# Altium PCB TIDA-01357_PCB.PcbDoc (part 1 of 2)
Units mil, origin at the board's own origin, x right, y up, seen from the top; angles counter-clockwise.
Board outline 1710 x 2300 mil, 4 copper layers (Top Layer, Mid Layer 1, Mid Layer 2, Bottom Layer), stack 79.8 mil thick; 69 components, 66 nets, 243 pads, 213 vias.
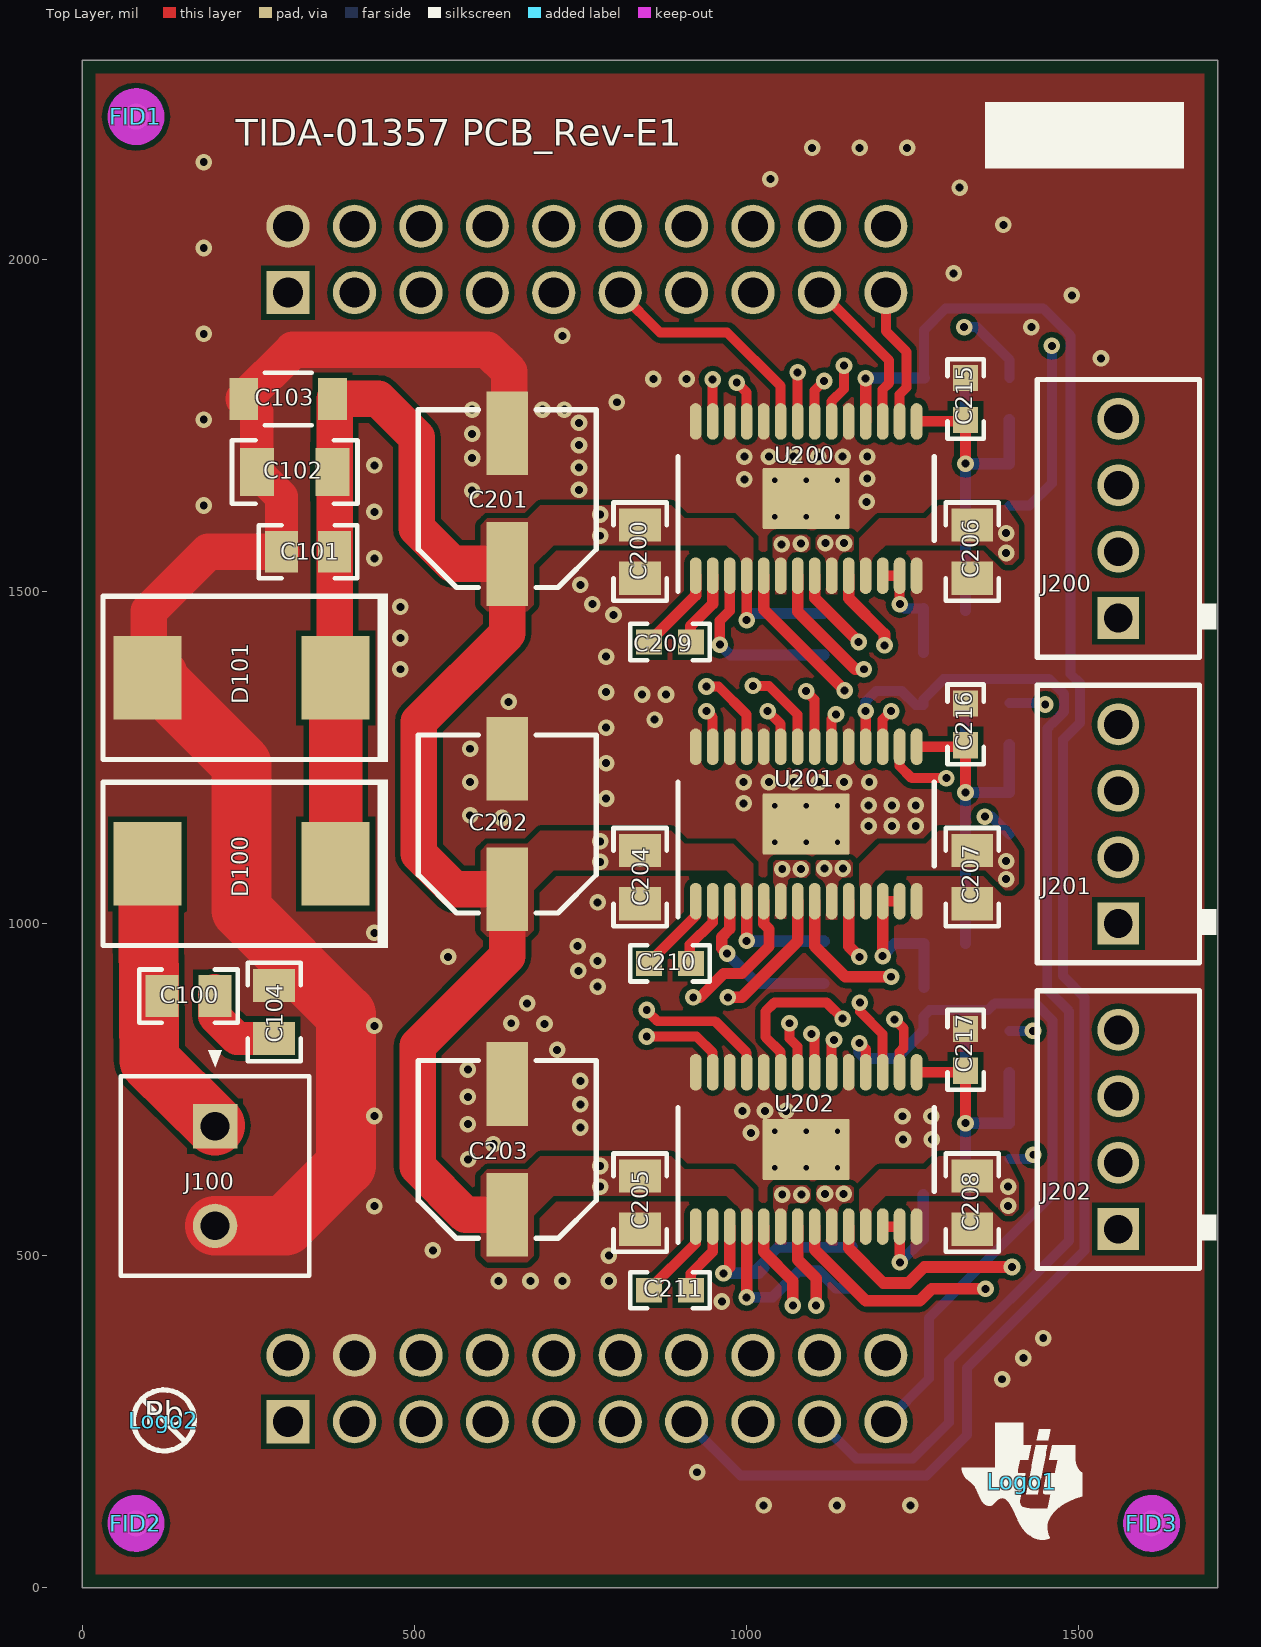
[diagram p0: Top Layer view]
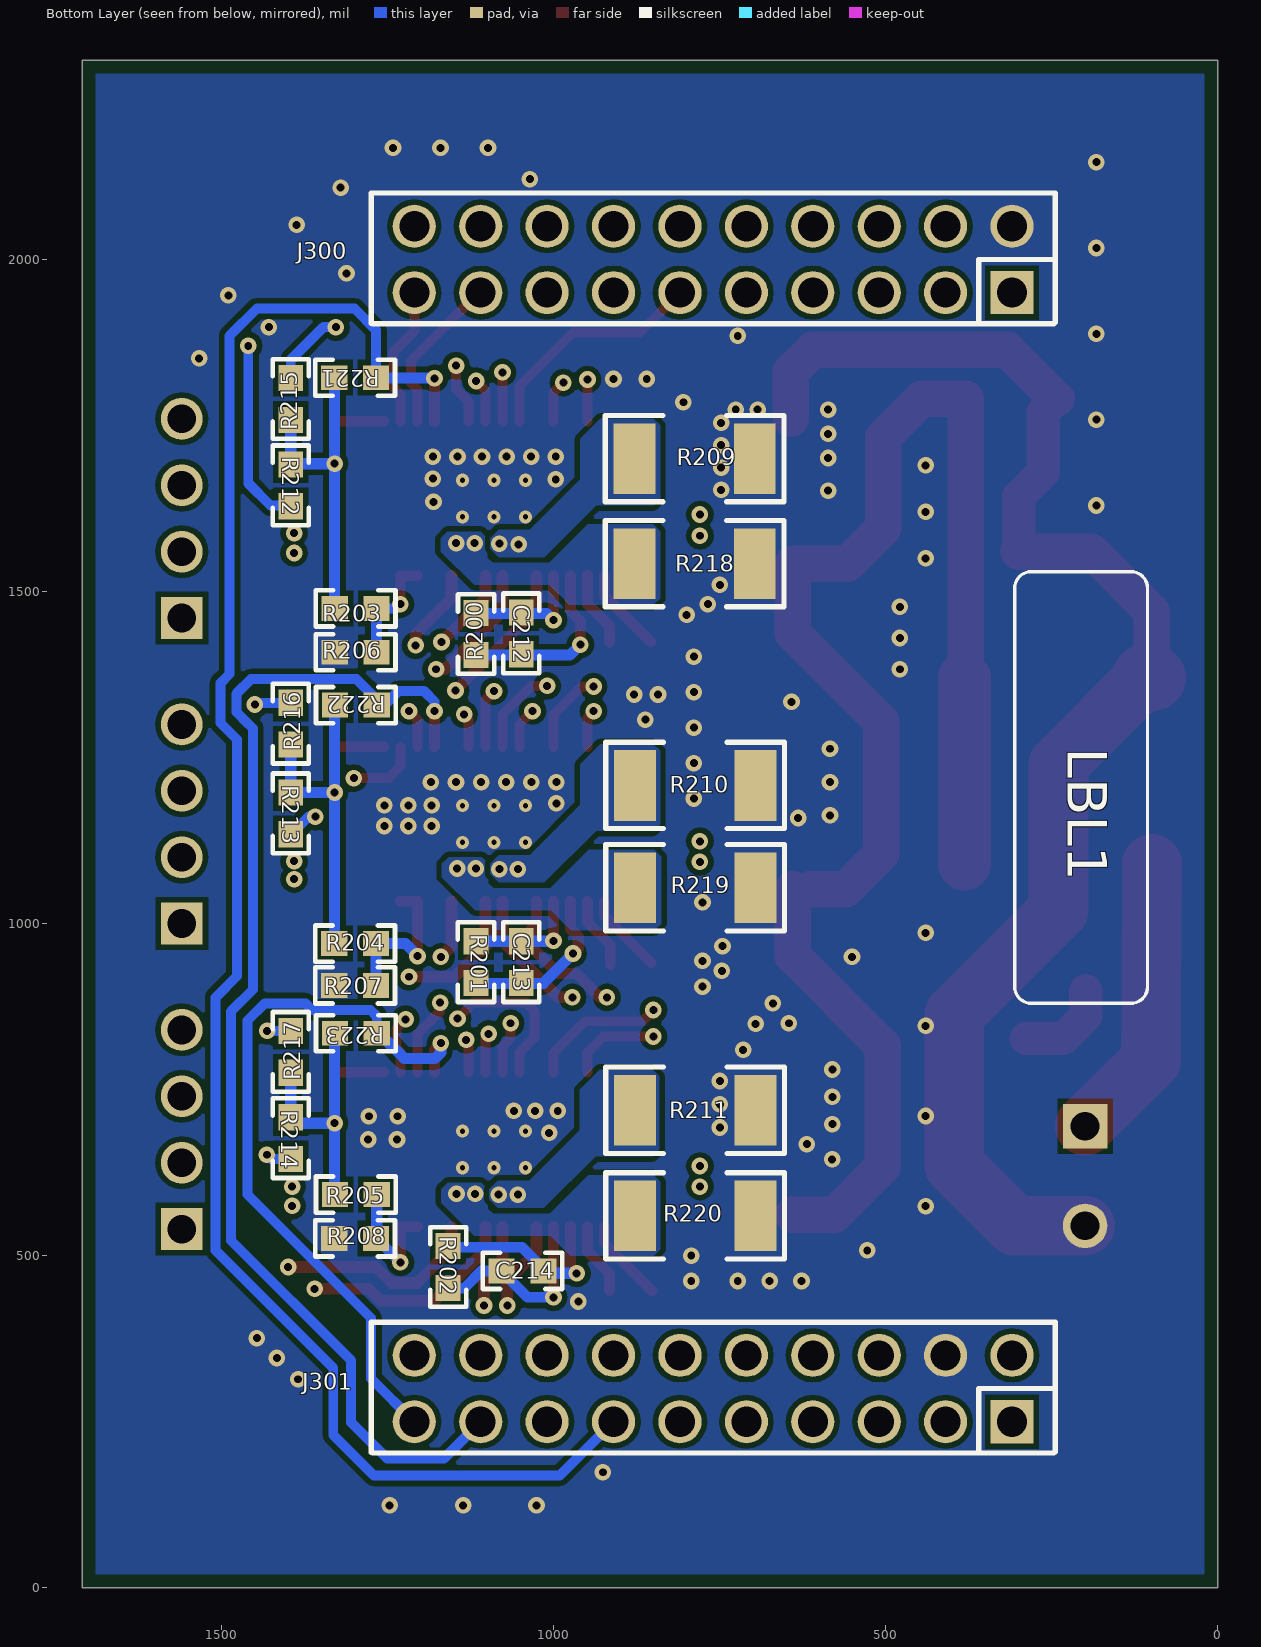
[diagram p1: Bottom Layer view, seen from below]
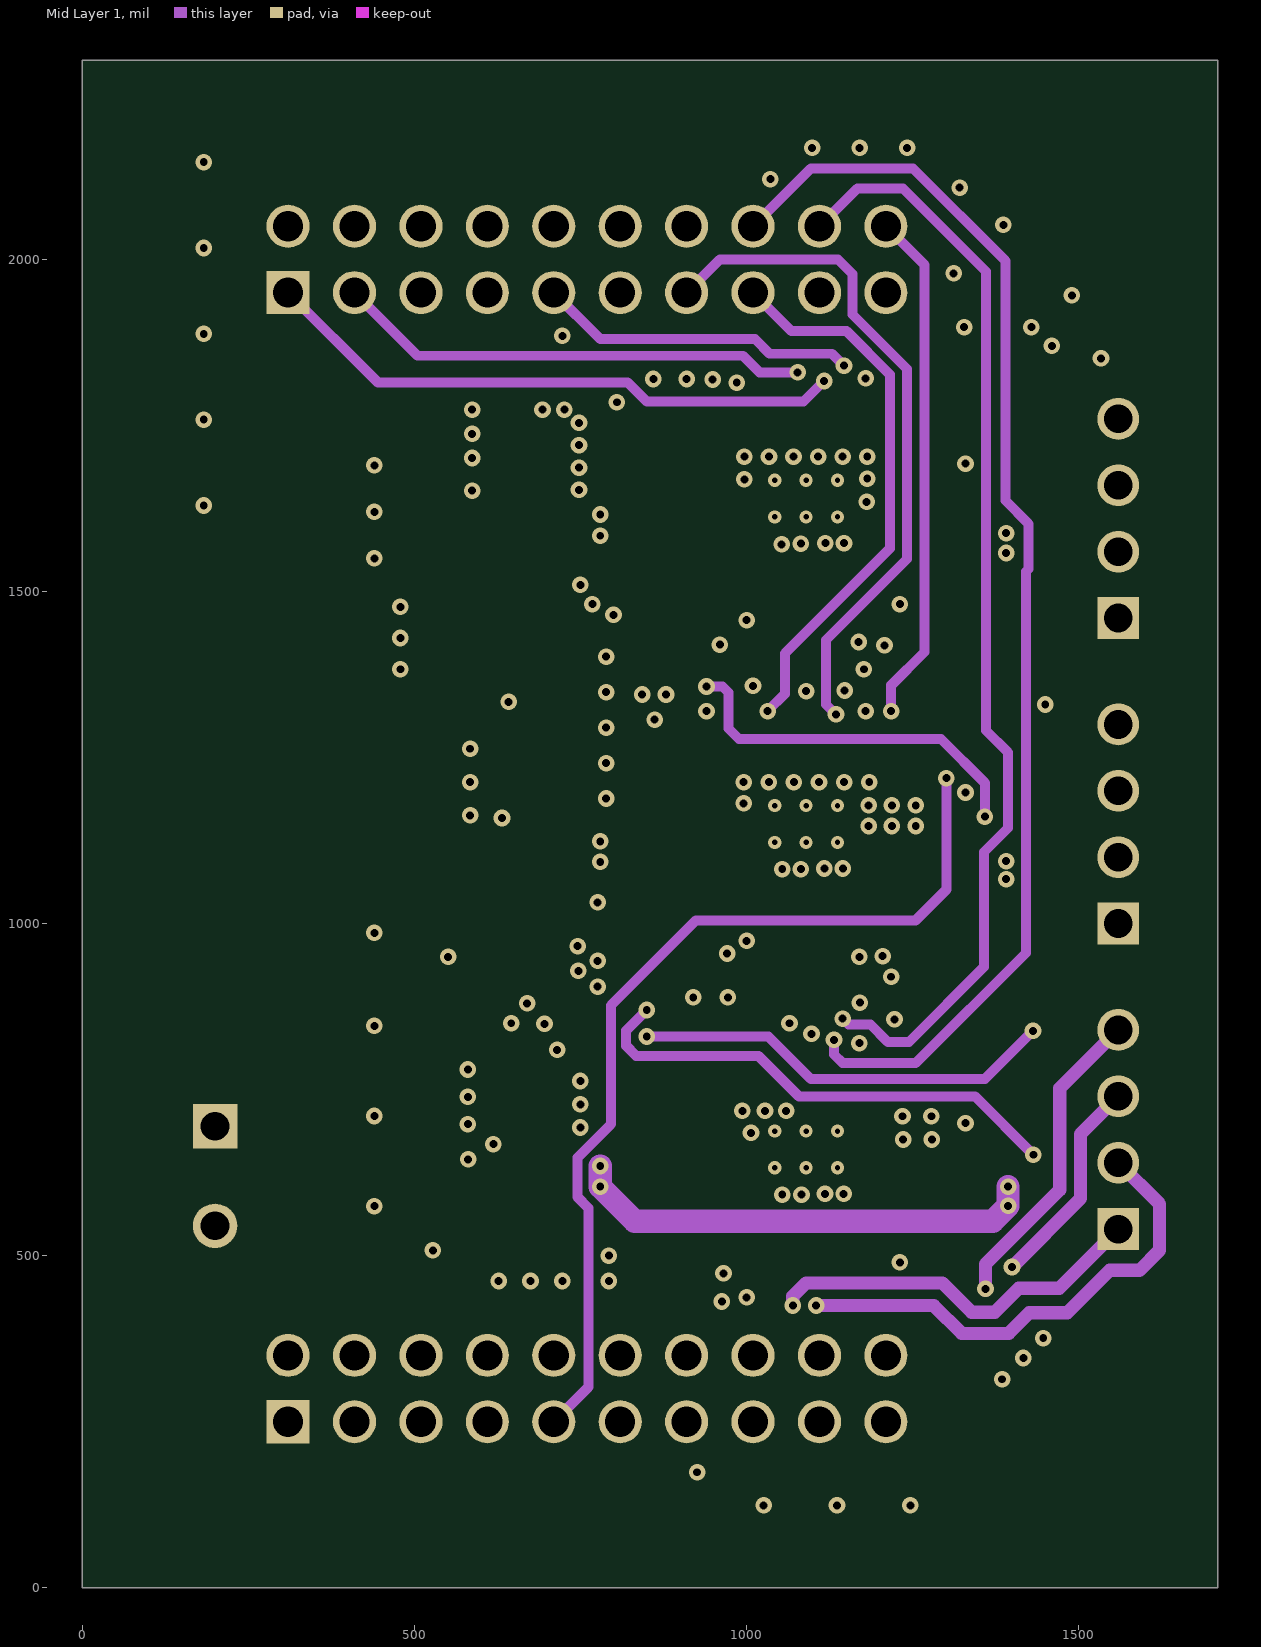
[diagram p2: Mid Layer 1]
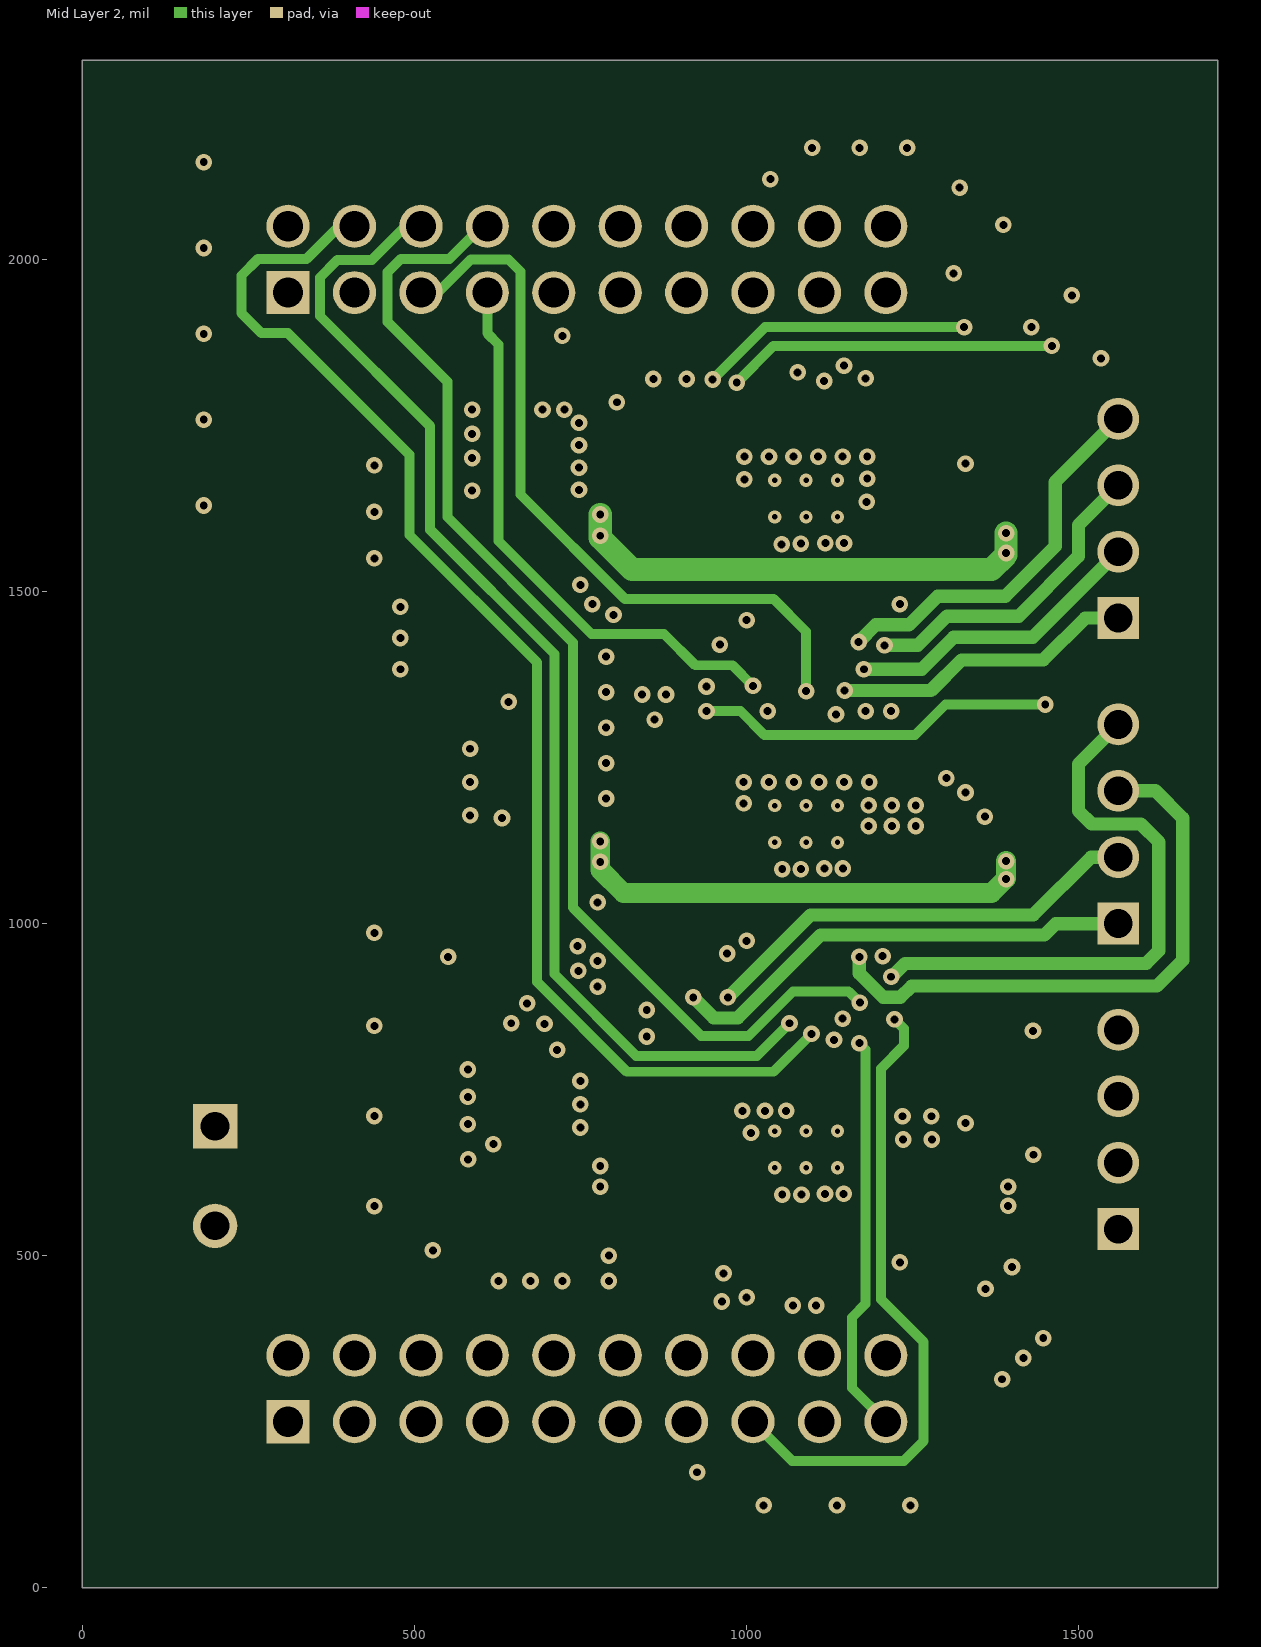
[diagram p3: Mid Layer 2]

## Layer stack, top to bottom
Top Solder: solder mask 0.4, Solder Resist, Dk 3.5
Top Layer: signal copper 1.4
Dielectric1: core 59.2, FR-4, Dk 4.8
Mid Layer 1: signal copper 1.4
Dielectric 2: prepreg 5, Dk 4.2
Mid Layer 2: signal copper 1.4
Dielectric 3: core 10, Dk 4.2
Bottom Layer: signal copper 1.4
Bottom Solder: solder mask 0.4, Solder Resist, Dk 3.5

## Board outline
0,0 0,2300 1710,2300 1710,0

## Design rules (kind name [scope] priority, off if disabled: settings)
AcuteAngle [All] p1: minimum=4.50000000000000E+0001 checktracksonly=FALSE
AssemblyTestPointUsage [All] p1: valid=2
BoardOutlineClearance BoardOutlineClearance_MountingHoles [OnCopper and InComponentClass('Mounting Holes')] p1: gap=20
BoardOutlineClearance BoardOutlineClearance_Poly [OnCopper and IsPoly] p2: gap=20
BoardOutlineClearance [OnCopper and Not InComponentClass('Logo') and not InComponentClass('FiducialMark') and not InRegion(1000,500,4000,800) and not InPoly] p3: gap=25
Clearance Clearance_Keepouts [((IsTrack Or IsArc) And Not InPoly) And IsFree and IsKeepOut vs ((IsTrack Or IsArc) And Not InPoly) And IsFree and IsKeepOut] p1: gap=0
Clearance Clearance_Poly [InPolygon] p2: gap=8
Clearance [All] p3: gap=7.87
ComponentClearance ComponentClearance_MountingHoles_FiducialMarks [InComponentClass('Mounting Holes') vs InComponentClass('FiducialMark')] p1: gap=50 collisioncheckmode=3 verticalgap=10 showdistances=FALSE
ComponentClearance ComponentClearance_Shunt [InComponentClass('Header') vs InComponentClass('Shunt')] p2: gap=0 collisioncheckmode=3 verticalgap=0 showdistances=FALSE
ComponentClearance ComponentClearance_Logo [InComponentClass('Logo')] p3: gap=50 collisioncheckmode=3 verticalgap=10 showdistances=FALSE
ComponentClearance ComponentClearance_ScrewToNut [(HasFootprint('NY PMS 440 0025 PH')) vs (HasFootprint('Keystone_1902C'))] p4: gap=5 collisioncheckmode=3 verticalgap=10 showdistances=FALSE
ComponentClearance ComponentClearance_MountingHoles [InComponentClass('Mounting Holes')] p5: gap=250 collisioncheckmode=3 verticalgap=100000 showdistances=FALSE
ComponentClearance ComponentClearance_SmallPassives [HasFootprint('0201*') or HasFootprint('0402*') or HasFootprint('0508') or HasFootprint('0603*') or HasFootprint('0612') or HasFootprint('0805*') or HasFootprint('0815*') or HasFootprint('0830*') or HasFootprint('1206*') or HasFootprint('1210*') or HasFootprint('1808*') or HasFootprint('1812*') or HasFootprint('1825*') or HasFootprint('2010*') or HasFootprint('2220*') or HasFootprint('2225*') or HasFootprint('2512*') or HasFootprint('2728*') or HasFootprint('3518*') vs HasFootprint('0201*') or HasFootprint('0402*') or HasFootprint('0508') or HasFootprint('0603*') or HasFootprint('0612') or HasFootprint('0805*') or HasFootprint('0815*') or HasFootprint('0830*') or HasFootprint('1206*') or HasFootprint('1210*') or HasFootprint('1808*') or HasFootprint('1812*') or HasFootprint('1825*') or HasFootprint('2010*') or HasFootprint('2220*') or HasFootprint('2225*') or HasFootprint('2512*') or HasFootprint('2728*') or HasFootprint('3518*')] p6: gap=14.96 collisioncheckmode=3 verticalgap=10 showdistances=FALSE
ComponentClearance ComponentClearance_THtoSMT [IsThruComponent vs IsSMTComponent] p7: gap=40 collisioncheckmode=3 verticalgap=30 showdistances=FALSE
ComponentClearance ComponentClearance_THtoTH [IsThruComponent vs IsThruComponent] p8: gap=30 collisioncheckmode=3 verticalgap=30 showdistances=FALSE
ComponentClearance [All] p9: gap=30 collisioncheckmode=3 verticalgap=10 showdistances=FALSE
DiffPairsRouting [All] p1: maxlimit=100 minlimit=10 mostfreqgap=10 toplayer_minwidth=15 toplayer_maxwidth=15 toplayer_prefwidth=15 midlayer1_minwidth=15 midlayer1_maxwidth=15 midlayer1_prefwidth=15 midlayer2_minwidth=15 midlayer2_maxwidth=15 midlayer2_prefwidth=15 bottomlayer_minwidth=15 bottomlayer_maxwidth=15 bottomlayer_prefwidth=15 maxuncoupledlength=1000
FabricationTestPointUsage TestPointUsage [All] p1: valid=2 allowmultiple=FALSE
FabricationTestpoint Testpoint [All] p1: side=3 testpointundercomponent=TRUE minsize=40 maxsize=100 preferedsize=60 minholesize=0 maxholesize=40 preferedholesize=32 testpointgrid=1 allowsidetop=TRUE allowsidebottom=TRUE usegrid=TRUE gridtolerance=0.01
FanoutControl Fanout_LCC [IsLCC] p1: bgadir=Out bgaviamode=Centered fanoutstyle=Auto fanoutdirection=Alternating viagrid=1 // Fanout_LCC (Default Rule)
FanoutControl Fanout_BGA [IsBGA] p2: bgadir=Out bgaviamode=Centered fanoutstyle=Auto fanoutdirection=Alternating viagrid=1 // Fanout_BGA (Default Rule)
FanoutControl Fanout_Default [All] p4: bgadir=Out bgaviamode=Centered fanoutstyle=Auto fanoutdirection=Alternating viagrid=1 // Fanout_Default (Default Rule)
FanoutControl Fanout_Small [(CompPinCount < 5)] p5: bgadir=Out bgaviamode=Centered fanoutstyle=Auto fanoutdirection=OutThenIn viagrid=1 // Fanout_Small (Default Rule)
HoleSize [All] p1: absolutevalues=TRUE maxlimit=251 minlimit=7.87 maxpercent=80.000 minpercent=20.000
MinimumAnnularRing MinimumAnnularRing_ThermalPadVias [IsVia and InAnyComponent] p1: minimumring=5.91
MinimumAnnularRing [All] p2: minimumring=6.5
MinimumSolderMaskSliver MinimumSolderMaskSliver_Logo [InComponentClass('Logo') vs InComponentClass('Logo')] p1: minsoldermaskwidth=0.7
MinimumSolderMaskSliver [All] p2 off: minsoldermaskwidth=3.94
PlaneConnect [All] p1: planeconnectstyle=Relief reliefexpansion=10 reliefentries=4 reliefconductorwidth=10 reliefairgap=10
PolygonConnect [All] p1: connectstyle=Direct reliefconductorwidth=10 reliefentries=4 polygonreliefangle="90 Angle" airgapwidth=10
RoutingVias ThermalPadVias [IsVia and InAnyComponent] p1: holewidth=12 width=29 viastyle="Through Hole" minholewidth=7.87 minwidth=19.68 maxholewidth=12.99 maxwidth=23.62
RoutingVias [All] p2: holewidth=12 width=29 viastyle="Through Hole" minholewidth=7.87 minwidth=25 maxholewidth=12 maxwidth=29
SilkToBoardRegionClearance [Not ((IsComment or IsDesignator) And (Hide <> 'False')) and not InRegion(1000,500,4000,800)] p1:
SilkToSilkClearance SilkToSilkClearance_Pb-FreeLogo [(HasFootprint('Pb-Free_Overlay_Medium') OR HasFootprint('Pb-Free_Overlay_Small')) vs (HasFootprint('Pb-Free_Overlay_Medium') OR HasFootprint('Pb-Free_Overlay_Small'))] p1: silktosilkclearance=0
SilkToSilkClearance [All] p2: silktosilkclearance=0
SilkToSolderMaskClearance SilkToComponentPadClearance [IsPad and InAnycomponent] p1: minsilkscreentomaskgap=0 clearancetoexposedcopper=TRUE
SilkToSolderMaskClearance "Silk to Solder Mask Opening" [All] p2 off: minsilkscreentomaskgap=0 clearancetoexposedcopper=FALSE
SolderMaskExpansion [All] p1: expansion=1.97
Width [All] p1: maxlimit=100 minlimit=6 preferedwidth=10 checkconnectedcopper=TRUE
15 further rules are at their usual default settings.

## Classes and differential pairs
component class TIDA-01357_BlankSheet: C5 C100 C101 C102 C103 C104 C200 C201 C202 C203 C204 C205 C206 C207 C208 C209 C210 C211 C212 C213 C214 C215 C216 C217 C? D100 D101 J100 J200 J201 J202 J300 J301 R200 R201 R202 R203 R204 R205 R206 R207 R208 R209 R210 R211 R212 R213 R214 R215 R216 R217 R218 R219 R220 R221 R222 R223 U200 U201 U202
component class Logo: Logo1
component class TIDA-01357_EVM_Hardware: FID1 FID2 FID3 LBL1 Logo1 Logo2 Logo3 ZZ1 ZZ2 ZZ3 ZZ4
component class FiducialMark: FID1 FID2 FID3
component class AssemblyNote: ZZ1 ZZ2 ZZ3 ZZ4
component class Label: LBL1

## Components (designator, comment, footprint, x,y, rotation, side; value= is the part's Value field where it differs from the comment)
C100 "GCM21BR72A473KA37L" 0805_HV 160,891 r0 top
C101 "GCM21BR71H104KA37K" 0805_HV 340,1560 r180 top
C102 "GCM31MR71H105KA55L" 1206 320,1680 r180 top
C103 "CGA5L3X5R1H106K160AB" 1206_190 310,1790 r180 top
C104 "GCM21BR72A473KA37L" 0805_HV 289,867 r90 top
C200 "GCM21BR71H104KA37K" 0805_HV 840,1560 r90 top
C201 "EEEFTH101XAP" Panasonic_D8 640,1640 r90 top
C202 "EEEFTH101XAP" Panasonic_D8 640,1150 r90 top
C203 "EEEFTH101XAP" Panasonic_D8 640,660 r90 top
C204 "GCM21BR71H104KA37K" 0805_HV 840,1070 r90 top
C205 "GCM21BR71H104KA37K" 0805_HV 840,580 r270 top
C206 "GCM21BR71H104KA37K" 0805_HV 1340,1560 r90 top
C207 "GCM21BR71H104KA37K" 0805_HV 1340,1070 r90 top
C208 "GCM21BR71H104KA37K" 0805_HV 1340,580 r90 top
C209 "GCM188R71H103KA37D" 0603 885,1424 r0 top
C210 "GCM188R71H103KA37D" 0603 885,940 r0 top
C211 "GCM188R71H103KA37D" 0603 885,448 r0 top
C212 "GCM188R71C104KA37J" 0603 1049,1437 r270 bottom
C213 "GCM188R71C104KA37J" 0603 1049,942 r270 bottom
C214 "GCM188R71C104KA37J" 0603 1047,477 r180 bottom
C215 "GCM188R71C474KA55D" 0603 1330,1790 r90 top
C216 "GCM188R71C474KA55D" 0603 1330,1300 r90 top
C217 "GCM188R71C474KA55D" 0603 1330,810 r90 top
D100 "SS3H10HE3_A/I" SMC_265 240,1090 r180 top
D101 "TPSMD26A" SMC_265 240,1370 r180 top
FID1 "Fiducial" Fiducial10-20 81,2215 r0 top
FID2 "Fiducial" Fiducial10-20 81,97 r0 top
FID3 "Fiducial" Fiducial10-20 1610,97 r0 top
J100 "1727010" PhoenixConact_1727010 200,620 r270 top
J200 "1725672" Phoenix_1725672 1560,1610 r90 top
J201 "1725672" Phoenix_1725672 1560,1150 r90 top
J202 "1725672" Phoenix_1725672 1560,690 r90 top
J300 "66953-010LF" FCI_66953-010LF 760,2000 r180 bottom
J301 "66953-010LF" FCI_66953-010LF 760,300 r180 bottom
LBL1 "Size: 0.65\" x 0.20 \"" Label_650x200 206,1205 r270 bottom
Logo1 "Texas Instruments" TI_Symbol_Overlay_Small 1415,160 r0 top
Logo2 "Pb-Free Symbol" Pb-Free_Overlay_Small 123,252 r0 top
Logo3 "FCC disclaimer" FCC_disclaimer 60.09,2780 r180 bottom
R200 "CRCW06031M00JNEA" 0603 1117,1436 r90 bottom
R201 "CRCW06031M00JNEA" 0603 1117.07,942 r90 bottom
R202 "CRCW06031M00JNEA" 0603 1159,483 r270 bottom
R203 "CRCW060310K0FKEA" 0603 1298.24,1474.54 r180 bottom
R204 "CRCW060310K0FKEA" 0603 1299,970 r180 bottom
R205 "CRCW060310K0FKEA" 0603 1298,592 r180 bottom
R206 "CRCW060310K0FKEA" 0603 1298.24,1408.54 r0 bottom
R207 "CRCW060310K0FKEA" 0603 1299,907 r0 bottom
R208 "CRCW060310K0FKEA" 0603 1299,526 r0 bottom
R209 "CSR2010JTR300" 2010 788,1700 r180 bottom
R210 "CSR2010JTR300" 2010 787,1208 r180 bottom
R211 "CSR2010JTR300" 2010 787,719 r180 bottom
R212 "ERA-3AEB5761V" 0603 1396,1660 r270 bottom
R213 "ERA-3AEB5761V" 0603 1395.93,1166 r270 bottom
R214 "ERA-3AEB5761V" 0603 1396,677 r270 bottom
R215 "ERA-3AEB5761V" 0603 1396,1790 r90 bottom
R216 "ERA-3AEB5761V" 0603 1396,1301 r90 bottom
R217 "ERA-3AEB5761V" 0603 1395.93,807 r90 bottom
R218 "CSR2010JTR300" 2010 788,1542 r180 bottom
R219 "CSR2010JTR300" 2010 787,1054 r180 bottom
R220 "CSR2010JTR300" 2010 787,560 r180 bottom
R221 "ERA-3AEB5761V" 0603 1299,1822 r0 bottom
R222 "ERA-3AEB5761V" 0603 1298,1329 r0 bottom
R223 "ERA-3AEB5761V" 0603 1298,835 r0 bottom
U200 "DRV8802QPWPRQ1" PWP0028H_N 1090,1640 r90 top
U201 "DRV8802QPWPRQ1" PWP0028H_N 1090,1150 r90 top
U202 "DRV8802QPWPRQ1" PWP0028H_N 1090,660 r90 top
ZZ1 "This Assembly Note is for PCB labels only" AssemblyNoteLabel -2105,3338 r0 top
ZZ2 "These assemblies are ESD sensitive, ESD precautions shall be observed." AssemblyNote -2105,3229.11 r0 top
ZZ3 "These assemblies must be clean and free from flux and all contaminants. Use of no clean flux is not acceptable." AssemblyNote -2105,3140.56 r0 top
ZZ4 "These assemblies must comply with workmanship standards IPC-A-610 Class 2, unless otherwise specified." AssemblyNote -2105,3052 r0 top

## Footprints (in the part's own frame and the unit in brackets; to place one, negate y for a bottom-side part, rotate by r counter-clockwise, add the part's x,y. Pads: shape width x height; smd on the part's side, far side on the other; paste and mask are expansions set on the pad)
0603 [mm] "0603 from SM-752 data"
  rect 1x0.95 smd: 1(-0.8,0) 2(0.8,0)
  silkscreen extent -1.52,-0.69 1.52,0.69, body extent -0.87,-0.47 0.87,0.47, height 1
0805_HV [mil] "0805 with 30mil clearance between pads"
  rect 50x63 smd: 1(-40,0) 2(40,0)
  silkscreen extent -74,-40 74,40, body extent -43,-29 43,29, height 57
1206 [mm] "1206 from SM-752 data"
  rect 1.3x1.85 smd: 1(-1.45,0) 2(1.45,0)
  silkscreen extent -2.4,-1.21 2.4,1.21, body extent -1.7,-0.9 1.7,0.9, height 1.35
1206_190 [mm] "1206_190"
  rect 1.1x1.6 smd: 1(-1.7,0) 2(1.7,0)
  silkscreen extent -0.9,-1 0.9,1, body extent -1.75,-0.95 1.75,0.95, height 1.9
2010 [mm] "Chip Capacitor, Body 5.08x2.54mm, IPC Medium Density"
  rect 1.6x2.7 smd: 1(-2.3,0) 2(2.3,0)
  silkscreen extent -3.42,-1.65 3.42,1.65, body extent -2.73,-1.45 2.73,1.45, height 1.66
AssemblyNote [mil] "Assembly Note"
AssemblyNoteLabel [mil] "Assembly Note for PCB Labels"
FCC_disclaimer [mil]
FCI_66953-010LF [mm] "FCI"
  rect 1.65x1.65 hole 1.15: 1(11.43,-1.27)
  round 1.65 hole 1.15: 2(11.43,1.27) 3(8.89,-1.27) 4(8.89,1.27) 5(6.35,-1.27) 6(6.35,1.27) 7(3.81,-1.27) 8(3.81,1.27) 9(1.27,-1.27) 10(1.27,1.27) 11(-1.27,-1.27) 12(-1.27,1.27) 13(-3.81,-1.27) 14(-3.81,1.27) 15(-6.35,-1.27) 16(-6.35,1.27) 17(-8.89,-1.27) 18(-8.89,1.27) 19(-11.43,-1.27) 20(-11.43,1.27)
  silkscreen extent -13.08,-2.46 13.08,2.54, body extent -13,-2.51 13,2.54, height 8.59
Fiducial10-20 [mm]
  round 1 smd mask+0.5: 1(0,0)
  Top Layer keep-out circle w1.178: c0,0 r0.5
Label_650x200 [mil] "Thermal Transfer Label"
  round 1 on Mech14: 0(0,0)
  silkscreen extent -325,-100 325,100, body extent -325,-100 325,100, height 1
Panasonic_D8 [mm] "SMD, 2-Leads, Dia 6.3mm"
  rect 3.2x1.6 smd: 1(-2.5,0) 2(2.5,0)
  silkscreen extent -3.4,-3.4 3.4,3.4, body extent -3.4,-3.4 3.4,3.4, height 8.01
Pb-Free_Overlay_Small [mil]
  silkscreen extent -46,-46 46,46
Phoenix_1725672 [mm] "Terminal Block, 4x1, 2.54 mm, TH"
  rect 1.6x1.6 hole 1.1: 1(-3.81,0)
  round 1.6 hole 1.1: 2(-1.27,0) 3(1.27,0) 4(3.81,0)
  silkscreen extent -5.31,-3.75 5.31,3.1, body extent -5.31,-3.1 5.31,3.1, height 9.01
PhoenixConact_1727010 [mm]
  rect 1.7x1.7 hole 1.1: 1(-1.905,0)
  round 1.7 hole 1.1: 2(1.905,0)
  silkscreen extent -4.8,-3.6 3.81,3.6, body extent -3.81,-3.6 3.81,3.7, height 8.52
PWP0028H_N [mm] "TSOP, 28-Leads, Body 9.7x4.4mm, Pitch 0.65mm, Exposed Pad, IPC Medium Density"
  rrect100% 1.4x0.45 smd: 1(-2.95,4.225) 2(-2.95,3.575) 3(-2.95,2.925) 4(-2.95,2.275) 5(-2.95,1.625) 6(-2.95,0.975) 7(-2.95,0.325) 8(-2.95,-0.325) 9(-2.95,-0.975) 10(-2.95,-1.625) 11(-2.95,-2.275) 12(-2.95,-2.925) 13(-2.95,-3.575) 14(-2.95,-4.225) 15(2.95,-4.225) 16(2.95,-3.575) 17(2.95,-2.925) 18(2.95,-2.275) 19(2.95,-1.625) 20(2.95,-0.975) 21(2.95,-0.325) 22(2.95,0.325) 23(2.95,0.975) 24(2.95,1.625) 25(2.95,2.275) 26(2.95,2.925) 27(2.95,3.575) 28(2.95,4.225)
  rrect4% 2.34x3.32 smd: 29(0,0)
  silkscreen extent -3.55,-4.9 1.6,4.9, body extent -3.21,-4.85 3.21,4.85, height 1
SMC_265 [mm] "SMD, 2-Leads, Body 7.15x6.25mm"
  rect 2.6x3.2 smd: 1(-3.6,0) 2(3.6,0)
  silkscreen extent -5.6,-3.22 5.3,3.23, body extent -4.07,-3.13 4.07,3.13, height 2.65
TI_Symbol_Overlay_Small [mil]
  silkscreen extent -90,-88 91,88

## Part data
C100 C104: "CAP, CERM, 0.047 µF, 100 V, +/- 10%, X7R, AEC-Q200 Grade 1, 0805"
C101 C200 C204 C205 C206 C207 C208: "CAP, CERM, 0.1 µF, 50 V, +/- 10%, X7R, AEC-Q200 Grade 1, 0805"
C102: "CAP, CERM, 1 µF, 50 V, +/- 10%, X7R, AEC-Q200 Grade 1, 1206"
C103: "CAP, CERM, 10 µF, 50 V, +/- 10%, X5R, 1206_190"
C201 C202 C203: "CAP, AL, 100 µF, 50 V, +/- 20%, 0.34 ohm, AEC-Q200 Grade 2, SMD"
C209 C210 C211: "CAP, CERM, 0.01 µF, 50 V, +/- 10%, X7R, AEC-Q200 Grade 1, 0603"
C212 C213 C214: "CAP, CERM, 0.1 µF, 16 V, +/- 10%, X7R, AEC-Q200 Grade 1, 0603"
C215 C216 C217: "CAP, CERM, 0.47 µF, 16 V, +/- 10%, X7R, AEC-Q200 Grade 1, 0603"
D100: "Diode, Schottky, 100 V, 3 A, AEC-Q101, SMC"
D101: "Diode, TVS, Uni, 26 V, 42.1 Vc, AEC-Q101, SMC"
FID1 FID2 FID3: "Fiducial mark.  There is nothing to buy or mount."
J100: "Conn Term Block, 2POS, 3.81mm, TH"
J200 J201 J202: "Terminal Block, 4x1, 2.54 mm, Green, TH"
J300 J301: "Receptacle, 100mil, 10X2, Tin, TH"
LBL1: library part THT-14-423-10, "Thermal Transfer Printable Labels, 0.650\" W x 0.200\" H - 10,000 per roll"
Logo1: library part TI_Logo, "Texas Instrument Corporate Signature"
Logo2: library part Pb-Free
Logo3: library part FCC_disclaimer, "FCC_disclaimer"
R200 R201 R202: "RES, 1.0 M, 5%, 0.1 W, 0603"
R203 R204 R205 R206 R207 R208: "RES, 10.0 k, 1%, 0.1 W, 0603"
R209 R210 R211 R218 R219 R220: "RES, 0.3, 5%, 1 W, 2010"
R212 R213 R214 R215 R216 R217 R221 R222 R223: "RES, 5.76 k, 0.1%, 0.1 W, AEC-Q200 Grade 0, 0603"
U200 U201 U202: "AUTOMOTIVE DC MOTOR DRIVER IC, PWP0028H (TSSOP-28)"
ZZ1: library part AssemblyNoteLabel
ZZ2 ZZ3 ZZ4: library part AssemblyNote

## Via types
v1: diameter 25, hole 12, Top Layer to Bottom Layer, tented both sides, 195 vias
v2: diameter 19.68, hole 7.87, Top Layer to Bottom Layer, 18 vias

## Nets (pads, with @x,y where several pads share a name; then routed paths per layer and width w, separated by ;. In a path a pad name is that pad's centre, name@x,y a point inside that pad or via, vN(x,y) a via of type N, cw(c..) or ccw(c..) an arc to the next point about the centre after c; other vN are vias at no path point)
1_AENBL: J300.1 U200.21 | length 954.5
  Top Layer w15: U200.21@1102.8,1756.14 1102.8,1802.8 v1(1117,1817)
  Mid Layer 1 w15: J300.1@310,1950 445,1815 821,1815 850,1786 1086,1786 v1(1117,1817)
1_AI1: R212.2 U200.25 | length 846.9
  Top Layer w15: v1(985.5,1814.5) 1000.43,1799.57 U200.25@1000.43,1756.14
  Mid Layer 2 w15: v1(985.5,1814.5) 1041,1870 v1(1460,1870)
  Bottom Layer w15: R212.2@1396,1629.5 1426.5,1629.5 1460,1663 v1(1460,1870)
1_AOUT1: J200.1 U200.5 | length 680.5
  Top Layer w17.5: U200.5@1026.02,1523.86 1026.02,1472.98 v1(1148,1351)
  Mid Layer 2 w20: v1(1148,1351) 1278,1351 1324,1397 1447,1397 1510,1460 J200.1@1560,1460
1_AOUT2: J200.2 U200.7 | length 646.1
  Top Layer w17.5: U200.7@1077.2,1523.86 1077.2,1469.8 1164,1383 v1(1177,1383)
  Mid Layer 2 w20: v1(1177,1383) 1264,1383 1312,1431 1431,1431 J200.2@1560,1560
1_APHASE: J300.9 U200.20 | length 574.1
  Top Layer w15: U200.20@1128.39,1756.14 1128.39,1786.39 1147,1805 v1(1147,1840)
  Mid Layer 1 w15: J300.9@710,1950 780,1880 1013,1880 1035,1858 1129,1858 v1(1147,1840)
1_BENBL: J300.3 U200.22 | length 790.6
  Top Layer w15: U200.22@1077.2,1756.14 v1(1077.2,1830)
  Mid Layer 1 w15: J300.3@410,1950 505,1855 995,1855 1020,1830 v1@1077,1830
1_BI1: R215.2 U200.27 | length 590.3
  Top Layer w15: U200.27@949.25,1756.14 v1(949.25,1819.25)
  Mid Layer 2 w15: v1(949.25,1819.25) 1028,1898 v1(1328,1898)
  Bottom Layer w15: v1(1328,1898) 1347,1898 1396,1849 R215.2@1396,1821.5
1_BOUT1: J200.3 U200.10 | length 606.6
  Top Layer w17.5: U200.10@1153.98,1523.86 1153.98,1490.02 1208,1436 v1(1208,1419)
  Mid Layer 2 w20: v1(1208,1419) 1258,1419 1302,1463 1410,1463 1500,1553 1500,1600 J200.3@1560,1660
1_BOUT2: J200.4 U200.8 | length 718.1
  Top Layer w17.5: U200.8@1102.8,1523.86 1102.8,1490.2 v1(1169,1424) v1@1171,1422
  Mid Layer 2 w20: v1(1169,1424) 1195,1450 1245,1450 1288,1493 1390,1493 1465,1568 1465,1665 J200.4@1560,1760 J200.4@1559,1760
1_BPHASE: J300.11 U200.23 | length 353.1
  Top Layer w15: J300.11@810,1950 870,1890 971,1890 1051.61,1809.39 U200.23@1051.61,1756.14
1_NFAULT: J301.13 R221.1 U200.18 | length 2714.5
  Top Layer w17: U200.18@1179.57,1756.14 v1(1179.57,1821)
  Bottom Layer w6: v1(1179.57,1821) v1@1180.06,1821.5
  Bottom Layer w15: J301.13@910,250 991,169 1271,169 1332,230 1332,331 1509,508 1509,889 1477,921 1477,1277 1502,1302 1502,1362 1488,1376 1488,1885 1447,1926 1300,1926 1267.5,1893.5 R221.1@1267.5,1822
  Bottom Layer w17: v1@1180.06,1821.5 R221.1@1268,1821.5
1_RESET: J300.19 U200.16 | length 210.9
  Top Layer w15: J300.19@1210,1950 1210,1892 1241,1861 1241,1807 1230.75,1796.75 U200.16@1230.75,1756.14
1_SLEEP: J300.17 U200.17 | length 243.2
  Top Layer w15: J300.17@1110,1950 1113,1950 1215,1848 1215,1814 1205.16,1804.16 U200.17@1205.16,1756.14
1_V3P3OUT: C215.1 R203.1 R212.1 R215.1 R221.2 U200.15 | length 622.9
  Top Layer w6: C215.1@1327.64,1756.14 C215.1@1330,1758.5
  Top Layer w16: U200.15@1256.34,1756.14 C215.1@1327.64,1756.14
  Top Layer w17: v1(1330,1692.5) C215.1@1330,1758.5
  Bottom Layer w6: R221.2@1330,1821.5 R221.2@1330.5,1822
  Bottom Layer w17: R203.1@1330,1472 v1(1330,1692.5) ; R221.2@1330,1821.5 v1(1330,1692.5) ; R215.1@1396,1758.5 1396,1692.5 v1(1330,1692.5)
2_AENBL: J300.5 U201.21 | length 1208.7
  Top Layer w15: v1(1090,1350) 1102.8,1337.2 U201.21@1102.8,1266.14
  Mid Layer 2 w15: J300.5@510,1950 535,1950 585,2000 642,2000 660,1982 660,1646 817,1489 1041,1489 1090,1440 v1(1090,1350)
2_AI1: R213.2 U201.25 | length 736
  Top Layer w15: v1(940,1357) 958,1357 1000.43,1314.57 U201.25@1000.43,1266.14
  Mid Layer 1 w15: v1(940,1357) 964,1357 973,1348 973,1294 989,1278 1293,1278 1359,1212 v1(1359,1161)
  Bottom Layer w15: v1(1359,1161) 1369.44,1161 R213.2@1395.93,1134.5
2_AOUT1: J201.1 U201.5 | length 929
  Top Layer w17: v1(920,889) 930,889 966,925 993.47,925 1034,965.53 1034,992 1026.02,999.98 U201.5@1026.02,1033.86
  Mid Layer 2 w20: v1(920,889) 951,858 987,858 1112,983 1449,983 1466,1000 J201.1@1560,1000
2_AOUT2: J201.2 U201.7 | length 876.1
  Top Layer w17.5: v1(972,889) 993,889 1077.2,973.2 U201.7@1077.2,1033.86
  Mid Layer 2 w20: v1(972,889) 973,889 1097.13,1013.13 1432.13,1013.13 1519,1100 J201.2@1560,1100
2_APHASE: J300.13 U201.20 | length 1085.1
  Top Layer w15: U201.20@1128.39,1266.14 1128.39,1308.39 v1(1135,1315)
  Mid Layer 1 w15: J300.13@910,1950 960,2000 1138,2000 1160,1978 1160,1917 1242,1835 1242,1549 1120,1427 1120,1330 v1(1135,1315)
2_BENBL: J300.7 U201.22 | length 988.1
  Top Layer w15: v1(1010,1358) 1034,1358 1077.2,1314.8 U201.22@1077.2,1266.14
  Mid Layer 2 w15: J300.7@610,1950 610,1889 627,1872 627,1576 767,1436 876,1436 923,1389 979,1389 v1(1010,1358)
2_BI1: R216.2 U201.27 | length 656.7
  Top Layer w15: v1(940,1320) 949.25,1310.75 U201.27@949.25,1266.14
  Mid Layer 2 w15: v1(940,1320) 991,1320 1027,1284 1254,1284 1300,1330 v1(1450,1330)
  Bottom Layer w15: R216.2@1396,1332.5 1447.5,1332.5 v1(1450,1330)
2_BOUT1: J201.3 U201.10 | length 968.6
  Top Layer w17.5: U201.10@1153.98,1033.86 1153.98,966.02 v1(1170,950)
  Mid Layer 2 w20: v1(1170,950) 1170,925 1206,889 1232,889 1249,906 1618,906 1657,945 1657,1159 1616,1200 J201.3@1560,1200
2_BOUT2: J201.4 U201.8 | length 1080.5
  Top Layer w17.5: U201.8@1102.8,1033.86 1102.8,966.2 1149,920 v1(1218,920)
  Mid Layer 2 w20: v1(1218,920) 1219,920 1239,940 1602,940 1621,959 1621,1123 1594,1150 1520,1150 1500,1170 1500,1240 J201.4@1560,1300
2_BPHASE: J300.15 U201.23 | length 902.1
  Top Layer w15: v1(1032,1320) 1051.61,1300.39 U201.23@1051.61,1266.14
  Mid Layer 1 w15: J300.15@1010,1950 1068,1892 1151,1892 1216,1827 1216,1565 1058,1407 1058,1346 v1(1032,1320)
2_NFAULT: J301.17 R222.1 U201.18 | length 1848.6
  Top Layer w16: U201.18@1179.57,1266.14 v1(1179.57,1320)
  Bottom Layer w6: R222.1@1266.07,1329.43 R222.1@1266.5,1329
  Bottom Layer w15: J301.17@1110,250 1165,195 1251,195 1305,249 1305,342 1486,523 1486,868 1453,901 1453,1294 1461.13,1302.13 1461.55,1302.13 1477.87,1318.45 1477.87,1318.87 1478,1319 1478,1346 1456,1368 1297,1368 1266.5,1337.5 R222.1@1266.5,1329 ; v1(1179.57,1320) 1179.57,1334.57 1195,1350 1234,1350 1254.57,1329.43 R222.1@1266.07,1329.43
2_RESET: J301.9 U201.16 | length 1527.7
  Top Layer w15: U201.16@1230.75,1266.14 1230.75,1237.25 1249,1219 v1(1301,1219)
  Mid Layer 1 w15: J301.9@710,250 762,302 762,572 746,588 746,648 796.06,698.06 796.06,877.06 924,1005 1255,1005 1301,1051 v1(1301,1219)
2_SLEEP: J300.20 U201.17 | length 833.9
  Top Layer w15: U201.17@1205.16,1266.14 1205.16,1307.16 v1(1218,1320)
  Mid Layer 1 w15: J300.20@1210,2050 1268,1992 1268,1409 1218,1359 v1(1218,1320)
2_V3P3OUT: C216.1 R204.1 R213.1 R216.1 R222.2 U201.15 | length 643.5
  Top Layer w6: C216.1@1327.64,1266.14 C216.1@1330,1268.5
  Top Layer w16: U201.15@1256.34,1266.14 C216.1@1327.64,1266.14
  Top Layer w17: v1@1330,1197 v1(1330,1197.5) C216.1@1330,1268.5
  Bottom Layer w6: R222.2@1329.5,1329 R222.2@1330,1328.5 ; R204.1@1330,970.5 R204.1@1330.5,970 ; R216.1@1395.93,1269.44 R216.1@1396,1269.5
  Bottom Layer w17: R204.1@1330,970.5 v1(1330,1197.5) ; R222.2@1330,1328.5 v1(1330,1197.5) ; R216.1@1395.93,1269.44 R213.1@1395.93,1197.5 v1(1330,1197.5)
3_AENBL: J300.4 U202.21 | length 2026.8
  Top Layer w15: v1(1098,834) 1102.8,829.2 U202.21@1102.8,776.14
  Mid Layer 2 w15: J300.4@412,2050 J300.4@410,2050 387,2050 338,2001 265,2001 240,1976 240,1919 270,1889 310,1889 493,1706 493,1585 685,1393 685,912 820,777 1041,777 v1(1098,834)
3_AI1: R214.2 U202.25 | length 993.6
  Top Layer w15: v1(850,870) 850,869 861.13,857.87 861.55,857.87 866.42,853 953,853 1000.43,805.57 U202.25@1000.43,776.14
  Mid Layer 1 w15: v1(850,870) 819,839 819,816 834,801 1018,801 1079,740 1344,740 v1(1432,652)
  Bottom Layer w15: R214.2@1396,645.5 1425.5,645.5 v1(1432,652)
3_AOUT1: J202.1 U202.5 | length 719.4
  Top Layer w17.5: U202.5@1026.02,543.86 1026.02,505.98 1070,462 v1(1070,425)
  Mid Layer 1 w20: v1(1070,425) 1070,439 1090,459 1295,459 1339,415 1374,415 1410,451 1471,451 J202.1@1560,540
3_AOUT2: J202.2 U202.7 | length 874.2
  Top Layer w17.5: U202.7@1077.2,543.86 1077.2,493.8 1105,466 v1(1105,425)
  Mid Layer 1 w20: v1(1105,425) 1282,425 1324,383 1395,383 1426,414 1483,414 1547,478 1592,478 1622,508 1622,578 J202.2@1560,640
3_APHASE: J300.16 U202.20 | length 1967.3
  Top Layer w15: U202.20@1128.39,776.14 1128.39,821.39 v1(1132,825)
  Mid Layer 1 w15: J300.16@1010,2050 1097,2137 1251,2137 1390,1998 1390,1637 1425,1602 1425,1534 1421,1530 1421,956 1255,790 1145,790 1132,803 v1(1132,825)
3_BENBL: J300.6 U202.22 | length 1883.3
  Top Layer w15: v1(1065,850) 1065,827 1077.2,814.8 U202.22@1077.2,776.14
  Mid Layer 2 w15: J300.6@510,2050 487,2050 436,1999 384,1999 358,1973 358,1915 524,1749 524,1593 711,1406 711,924 834,801 1016,801 v1(1065,850)
3_BI1: R217.2 U202.27 | length 813.2
  Top Layer w15: v1(850,830) 925,830 949.25,805.75 U202.27@949.25,776.14
  Mid Layer 1 w15: v1(850,830) 1033,830 1097,766 1359,766 v1@1432,839
  Bottom Layer w15: R217.2@1395.93,838.5 v1(1431.5,838.5)
3_BOUT1: J202.3 U202.10 | length 633.6
  Top Layer w17.5: U202.10@1153.98,543.86 1153.98,511.02 1206,459 1244,459 1268,483 v1(1400,483)
  Mid Layer 1 w20: v1(1400,483) 1503,586 1503,683 J202.3@1560,740
3_BOUT2: J202.4 U202.8 | length 806.1
  Top Layer w17.5: U202.8@1102.8,543.86 1102.8,509.2 1180,432 1261,432 1279,450 v1(1360,450)
  Mid Layer 1 w20: v1@1360,448 v1(1360,450) 1360,487 1472,599 1472,752 J202.4@1560,840
3_BPHASE: J300.18 U202.23 | length 1908.8
  Top Layer w15: U202.23@1051.61,776.14 1051.61,806.39 1029,829 1029,868 1042,881 1121,881 v1(1145,857)
  Mid Layer 1 w15: J300.18@1110,2050 1167,2107 1236,2107 1361,1982 1361,1291 1394,1258 1394,1144 1358,1108 1358,935 1245,822 1213,822 1187,848 1154,848 v1(1145,857)
3_NFAULT: J301.19 R223.1 U202.18 | length 1725
  Top Layer w16: v1(1170,820) 1179.57,810.43 U202.18@1179.57,776.14
  Mid Layer 2 w15: v1(1170,820) 1179.57,810.43 1179.57,427.57 1159,407 1159,301 J301.19@1210,250
  Bottom Layer w15: J301.19@1210,250 1275,315 1275,406 1461,592 1461,854 1435,880 1374,880 1364,870 1276,870 1266.5,860.5 R223.1@1266.5,838
  Bottom Layer w17: v1(1170,820) 1170,806 1179,797 1225,797 1265,837 R223.1@1265.5,837
3_RESET: J301.15 U202.16 | length 1063.5
  Top Layer w15: v1(1223,856) 1236.98,842.02 1236.98,812.98 1230.75,806.75 U202.16@1230.75,776.14
  Mid Layer 2 w15: J301.15@1010,250 1069,191 1237,191 1267,221 1267,370 1203,434 1203,782 1237,816 1237,842 v1(1223,856)
3_SLEEP: J300.8 U202.17 | length 1917.9
  Top Layer w15: v1(1171,881) 1171,868 1205.16,833.84 U202.17@1205.16,776.14
  Mid Layer 2 w15: J300.8@611,2050 J300.8@610,2050 602,2050 553,2001 480,2001 460,1981 460,1906 550,1816 550,1612 739,1423 739,1024 932,831 1003,831 1070,898 1154,898 v1(1171,881)
3_V3P3OUT: C217.1 R205.1 R214.1 R217.1 R223.2 U202.15 | length 542.3
  Top Layer w6: C217.1@1327.64,776.14 C217.1@1330,778.5
  Top Layer w16: U202.15@1256.34,776.14 C217.1@1327.64,776.14
  Top Layer w17: v1@1330,699 v1(1330,699.5) C217.1@1330,778.5
  Bottom Layer w6: R223.2@1329.5,838 R223.2@1330,837.5
  Bottom Layer w17: R205.1@1330,592 v1(1330,699.5) ; R223.2@1330,837.5 v1(1330,699.5) ; R217.1@1395.93,775.5 1395.93,699.5 v1(1330,699.5)
12V: C100.1 D100.2 J100.1 | length 435.4
  Top Layer w90: D100.2@99.25,1090 100.4,890.89 100.58,859.89 100.96,793.91 J100.1@200,696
